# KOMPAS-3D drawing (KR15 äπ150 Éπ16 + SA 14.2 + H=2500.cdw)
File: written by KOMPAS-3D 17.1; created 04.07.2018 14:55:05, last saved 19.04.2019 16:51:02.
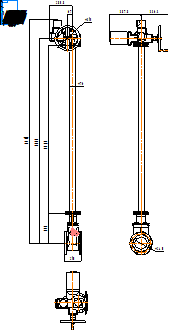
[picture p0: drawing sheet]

Sheet 1: A4, portrait

Title block, sheet 1: name: KR15 Ду150 Ру16 + / SA 14.2 + H=2500; material: Внимание! Данный продукт является объектом авторского права ООО «Торговый Дом АДЛ». / Запрещается изменение, копирование, распространение / (в том числе путем копирования на другие сайты и ресурсы в Интернете) / или любое иное использование информации и объектов без предварительного / согласия правообладателя (ООО «Торговый Дом АДЛ»).; mass: 36,7; sheets: 1; organisation: ООО "Торговый дом АДЛ"; sheet format: A4; stored path: \\adlc.lan\data\АДЛ_ПКД\3D-модели\ADL production\Клиновые задвижки серии KR ГРАНАР\Клиновые задвижки KR15 со стационарным удлинением\KOMPAS 2D\KR15 Ду150 Ру16 + SA 14.2 + H=2500.cdw

Views: Проекционный вид 6, Спереди 11, Проекционный вид 12
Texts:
  kka
  adl
Dimensions and other numbers on the sheet: 2500; 2045; 2731; 315; 76; 370; 210; 240; 336,3; 387,8; 67; 285,8; 1:1; 1; 36,7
